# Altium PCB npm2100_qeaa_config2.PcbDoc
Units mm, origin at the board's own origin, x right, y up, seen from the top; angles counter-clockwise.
Board outline 11.5 x 9 mm, 2 copper layers (Top Layer, Bottom Layer), stack 1.571 mm thick; 8 components, 12 nets, 31 pads, 23 vias.
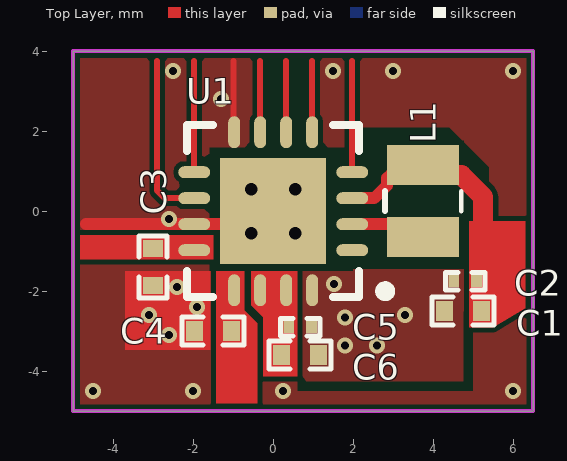
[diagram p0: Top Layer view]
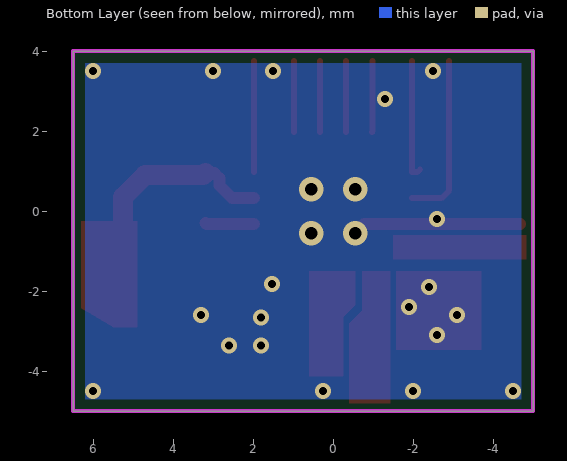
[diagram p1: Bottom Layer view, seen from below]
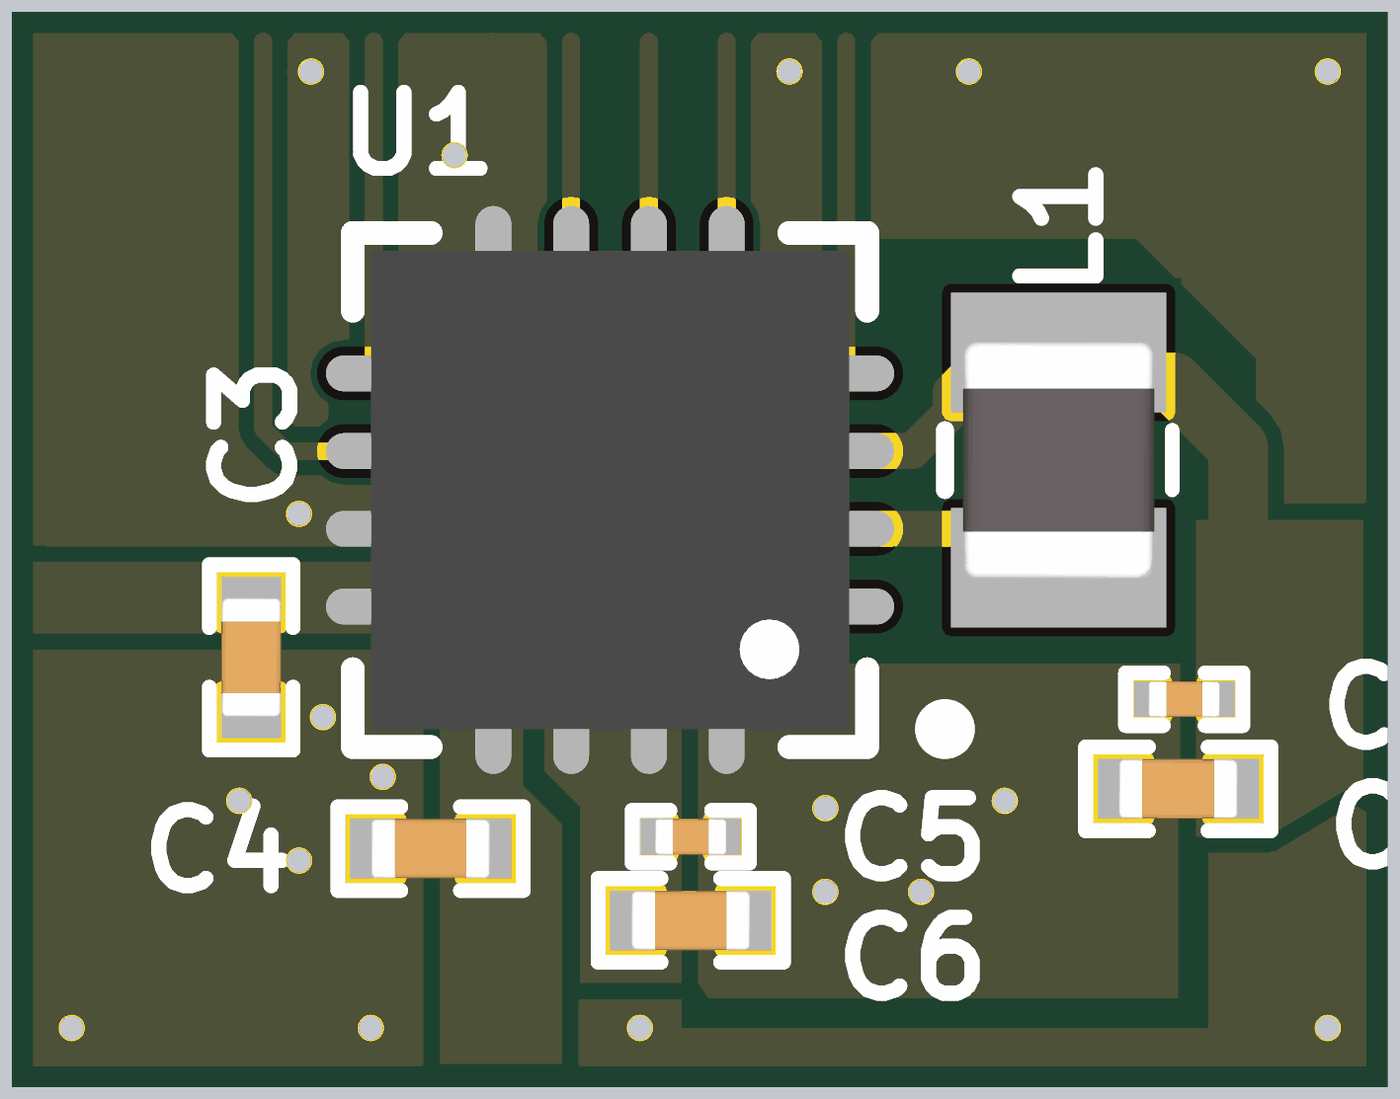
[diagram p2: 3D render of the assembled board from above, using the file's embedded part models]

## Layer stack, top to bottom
Top Solder: solder mask 0.0102, Solder Resist, Dk 3.5
Top Layer: signal copper 0.0356
Dielectric2: core 1.5, FR-4, Dk 4.8
Bottom Layer: signal copper 0.0356
Bottom Solder: solder mask 0.0102, Solder Resist, Dk 3.5

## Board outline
-5,-5 6.5,-5 6.5,4 -5,4

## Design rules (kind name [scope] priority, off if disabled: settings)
BoardOutlineClearance [All] p1: gap=0.15 ignorepadtopadclearanceinfootprint=FALSE
Clearance Polygon_Clearance [(InNamedPolygon('Top_Layer-GND')) or (InNamedPolygon('Bottom_Layer-GND')) or (InNamedPolygon('Mid_Layer_1-GND')) or (InNamedPolygon('Mid_Layer_2-GND'))] p1: gap=0.254 ignorepadtopadclearanceinfootprint=FALSE except(0: Arc-Hole Track-Hole SMDPad-Hole THPad-Hole Via-Hole Fill-Hole Poly-Hole Region-Hole Text-Hole)
Clearance [All] p2: gap=0.125 ignorepadtopadclearanceinfootprint=FALSE
ComponentClearance [All] p1 off: gap=0.254 collisioncheckmode=3 verticalgap=0.254 showdistances=FALSE
DiffPairsRouting [All] p1: maxlimit=0.15 minlimit=0.15 mostfreqgap=0.15 toplayer_minwidth=0.15 toplayer_maxwidth=0.15 toplayer_prefwidth=0.15 bottomlayer_minwidth=0.15 bottomlayer_maxwidth=0.15 bottomlayer_prefwidth=0.15 impedanceprofiledriven=TRUE maxuncoupledlength=12.7
FabricationTestPointUsage TestPointUsage [All] p1: valid=0 allowmultiple=FALSE
FabricationTestpoint Testpoint [All] p1: side=3 testpointundercomponent=TRUE minsize=1.016 maxsize=2.54 preferedsize=1.524 minholesize=0 maxholesize=1.016 preferedholesize=0.813 testpointgrid=0.025 allowsidetop=TRUE allowsidebottom=TRUE usegrid=TRUE gridtolerance=0
Height [All] p1 off: minheight=0 maxheight=25.4 prefheight=12.7
HoleSize [All] p1: absolutevalues=TRUE maxlimit=5 minlimit=0.1 maxpercent=80.000 minpercent=20.000
MinimumAnnularRing [All] p1 off: minimumring=0.1
MinimumSolderMaskSliver [All] p1: minsoldermaskwidth=0.03
PolygonConnect PolygonConnect_GND [InNet('GND')] p1: connectstyle=Direct reliefconductorwidth=0.254 reliefentries=4 polygonreliefangle="90 Angle" airgapwidth=0.254
PolygonConnect [All] p2: connectstyle=Direct reliefconductorwidth=0.254 reliefentries=4 polygonreliefangle="90 Angle" airgapwidth=0.254
RoutingVias [All] p1: holewidth=0.3 width=0.6 viastyle="Through Hole" minholewidth=0.2 minwidth=0.4 maxholewidth=0.5 maxwidth=1
ShortCircuit ShortCircuit_PVSS [InNet('PVSS1') or InNet('PVSS2') or InNet('PVSS3') vs InNet('GND')] p1: allowed=TRUE
ShortCircuit [All] p2: allowed=FALSE
SilkToSilkClearance [All] p1: silktosilkclearance=0.1
SilkToSolderMaskClearance SilkscreenOverComponentPads [IsPad] p1: minsilkscreentomaskgap=0.254 clearancetoexposedcopper=TRUE
SolderMaskExpansion SolderMaskExpansion_Vias [IsVia] p1: expansion=0.102 istentingtop=TRUE
SolderMaskExpansion [All] p2: expansion=0.075 istentingtop=FALSE
UnRoutedNet [All] p1: checkbadconnections=TRUE
Width [All] p1: maxlimit=2 minlimit=0.12 preferedwidth=0.3
19 further rules are at their usual default settings.

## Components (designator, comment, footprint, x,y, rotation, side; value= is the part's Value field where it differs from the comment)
C1 "10µF" CAPC1005X04L_C2 4.75,-2.5 r0 top
C2 "1nF" CAPC0603X03L_C 4.8,-1.75 r0 top
C3 "2.2µF" CAPC1005X04L_C2 -3,-1.4 r90 top
C4 "2.2µF" CAPC1005X04L_C2 -1.5,-3 r0 top
C5 "1nF" CAPC0603X03L_C 0.675,-2.9 r180 top
C6 "22µF" CAPC1005X04L_C2 0.675,-3.6 r180 top
L1 "2.2µH" INDC2016X18N 3.75,0.25 r270 top
U1 "nPM2100-QEAA" QFN65P400X400X65_HS-17N 0,0 r180 top

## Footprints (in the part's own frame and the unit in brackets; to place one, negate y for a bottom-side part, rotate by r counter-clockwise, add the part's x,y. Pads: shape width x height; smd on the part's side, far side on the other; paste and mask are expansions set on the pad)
CAPC0603X03L_C [mm] "Chip Capacitor, 2-Leads, Body 0.6x0.3mm, IPC High Density"
  rect 0.27x0.3 smd mask+0.05: 1(-0.285,0) 2(0.285,0)
  silkscreen extent -0.49,-0.22 0.49,0.22, body extent -0.3,-0.15 0.3,0.15, height 0.3
CAPC1005X04L_C2 [mm] "Chip Capacitor, 2-Leads, Body 1.0x0.5mm, IPC High Density"
  rect 0.425x0.5 smd mask+0.05: 1(-0.463,0) 2(0.463,0)
  silkscreen extent -0.77,-0.35 0.77,0.35, body extent -0.5,-0.25 0.5,0.25, height 0.5
INDC2016X18N [mm] "Chip Inductor, 2-Leads, Body 2,00x1,60mm, IPC Medium Density"
  rect 1x1.8 smd: 1(-0.9,0) 2(0.9,0)
  silkscreen extent -0.25,-0.95 0.25,0.95, body extent -1,-0.8 1,0.8, height 1.8
QFN65P400X400X65_HS-17N [mm] "QFN, 16-Leads, Body 4.00x4.00mm, Pitch 0.65mm, Thermal Pad 2.65x2.65mm, IPC Medium Density"
  oval 0.8x0.3 smd: 1(-1.975,0.975) 2(-1.975,0.325) 3(-1.975,-0.325) 4(-1.975,-0.975) 9(1.975,-0.975) 10(1.975,-0.325)
  oval 0.3x0.8 smd: 5(-0.975,-1.975) 6(-0.325,-1.975) 7(0.325,-1.975)
  oval 0.3x0.8 smd mask+0: 8(0.975,-1.975) 13(0.975,1.975) 14(0.325,1.975) 15(-0.325,1.975) 16(-0.975,1.975)
  oval 0.8x0.3 smd mask+0: 11(1.975,0.325) 12(1.975,0.975)
  rect 2.65x2.65 smd: 17(0,0)
  silkscreen extent -2.93,-2.15 2.15,2.15, body extent -2,-2 2,2, height 0.65

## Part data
C1: library part C0402-10µ-6.3V-X5R-GRM155R60J106ME05D, "Capacitor, X5R, ±20%, 6.3V", Manufacturer=Murata, Manufacturer Part Number=GRM155R60J106ME05D, Part number IPS=N.A., Part number NEMS=100200554, Supplier Part Number 1=490-GRM155R60J106ME05DTR-ND
C2 C5: library part C0201-1n0-50V-X7R, "Capacitor, X7R, ±10pF, 50V", Manufacturer=Murata, Manufacturer Part Number=GRM033R71H102KA12D, Part number IPS=N.A., Part number NEMS=100200404, Supplier Part Number 1=490-10682-1-ND
C3 C4: library part C0402-2µ2-16V-X6S-GRM155C81C225KE11D, "Capacitor, X6S, ±10%, 16V", Manufacturer=Murata, Manufacturer Part Number=GRM155C81C225KE11D, Part number IPS=N.A., Part number NEMS=100200556, Supplier Part Number 1=490-14595-2-ND
C6: library part C0402-22µ-6.3V-X5R-GRM158R60J226ME01D, "Capacitor, X5R, ±20%, 6.3V", Manufacturer=Murata, Manufacturer Part Number=GRM158R60J226ME01D, Part number IPS=N.A., Part number NEMS=100200555, Supplier Part Number 1=490-GRM158R60J226ME01DTR-ND
L1: library part L0806-2µ2-1.2A-137.5mOhm-MLP2016H2R2MT0S1, "Shielded Multilayer Inductor, 1.2A, ±20%, 137.5mOhm", Manufacturer="TDK Corporation", Manufacturer Part Number=MLP2016H2R2MT0S1, Part number IPS=N.A., Part number NEMS=100300426, Supplier Part Number 1=445-15724-1-ND
U1: "Boost converter companion PMIC for maximum energy extraction of primary (no-rechargeable) batteries", Manufacturer="Nordic Semiconductor", Manufacturer Part Number=nPM2100_QEAA, Part number IPS=N.A., Part number NEMS=102000298

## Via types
v1: diameter 0.4, hole 0.2, Top Layer to Bottom Layer, tented both sides, 19 vias
v2: diameter 0.61, hole 0.305, Top Layer to Bottom Layer, tented both sides, 4 vias

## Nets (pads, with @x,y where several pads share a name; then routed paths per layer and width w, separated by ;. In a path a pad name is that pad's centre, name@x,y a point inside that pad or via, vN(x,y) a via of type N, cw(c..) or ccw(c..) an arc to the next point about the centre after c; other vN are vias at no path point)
GND: C1.1 C2.1 C3.1 C4.1 C5.1 C6.1 U1.8 U1.11 U1.16 U1.17 | length 6
  Top Layer w0.15: -0.987,3.75 -0.987,1.987 U1.8
  Top Layer w0.3: -4.675,-0.325 -3.303,-0.325 -3.253,-0.325 U1.11 -0.775,-0.325 v2(-0.55,-0.55)
  other v1: -4.5,-4.5 -2,-4.5 0.25,-4.5 6,-4.5 1.8,-3.362 2.6,-3.362 -2.6,-3.1 1.8,-2.662 -3.1,-2.6 3.3,-2.6 -1.9,-2.4 -2.4,-1.9 1.525,-1.825 -2.6,-0.2 -1.3,2.8 -2.5,3.5 1.5,3.5 3,3.5 6,3.5
  other v2: 0.55,-0.55 -0.55,0.55 0.55,0.55
GPIO0: U1.5 | length 1.8
  Top Layer w0.15: U1.5 0.975,3.75
GPIO1: U1.9 | length 3
  Top Layer w0.15: U1.9@-2.175,1.044 -2.106,0.975 U1.9 -1.975,3.75
PG/RESET: U1.10 | length 4.2
  Top Layer w0.15: -2.9,3.75 -2.9,0.513 -2.712,0.325 U1.10
SCL: U1.7 | length 1.8
  Top Layer w0.15: U1.7 -0.325,3.75
SDA: U1.6 | length 1.8
  Top Layer w0.15: U1.6 0.325,3.75
SHPHLD: U1.4 | length 2.8
  Top Layer w0.15: U1.4 1.975,3.75
SW: L1.2 U1.2 | length 1.2
  Top Layer w0.3: U1.2 3.174,-0.325 L1.2@3.199,-0.3
VBAT: C1.2 C2.2 L1.1 U1.3 | length 5.3
  Top Layer w0.3: U1.3 2.525,0.325 2.849,0.649 2.849,0.825 2.974,0.95 L1.1@3.199,0.95
  Top Layer w0.5: L1.1@3.199,0.95 3.249,0.9 4.707,0.9 5.25,0.357 5.25,-1.08
VINT: C5.2 C6.2 U1.14 U1.15
VOUT: C4.2 U1.13
VOUTLDO: C3.2 U1.12 | length 2.4
  Top Layer w0.3: C3.2@-3.037,-0.975 U1.12
  Top Layer w0.4: -4.475,-0.937 -4,-0.937 ; -3.963,-0.937 C3.2@-3.1,-0.937
pads on no net: U1.1

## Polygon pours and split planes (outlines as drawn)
GND on Bottom Layer "Bottom_Layer-GND" (solid, remove dead copper, pour order 7): -5,-5 -5,5 7.5,5 7.5,-5
GND on Top Layer "NONET_L-01_P-001" (solid, pour order 8): -5,-5 6.5,-5 6.5,4 -5,4

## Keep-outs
Keep-Out Layer:
  the board outline again, w0.1

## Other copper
Top Layer:
  pour cut-out: -1.6,1.6 -1.6,-1.5 2,-1.5 2,1.6
  pour cut-out: 4.75,-2.5 4.75,-4.25 0.6,-4.25 0.6,-4.5 5,-4.5 5,-2.5
  region net VBAT: 6.3,-0.25 4.9,-0.25 4.9,-2.9 5.5,-2.9 6.3,-2.42
  region net VOUTLDO: -4.825,-1.2 -1.5,-1.2 -1.5,-0.6 -4.825,-0.6
  region net VINT: 0.6,-4.125 0.6,-1.5 -0.55,-1.5 -0.55,-2.35 -0.25,-2.65 -0.25,-4.125
  region net VOUT: -0.4,-4.8 -0.4,-2.8 -0.725,-2.475 -0.725,-1.5 -1.425,-1.5 -1.425,-4.8
  region net GND: -3.7,-3.462 -3.7,-1.5 -1.575,-1.5 -1.575,-3.462
  pour cut-out: 2,2.1 4.4,2.1 5.4,1.1 5.4,-1.45 2,-1.45

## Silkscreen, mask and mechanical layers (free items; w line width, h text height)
Mechanical 1:
  the board outline again, w0.2

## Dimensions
-5,-5 to 6.5,-5 on Mechanical 3
6.5,4 to 6.5,-5 on Mechanical 3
